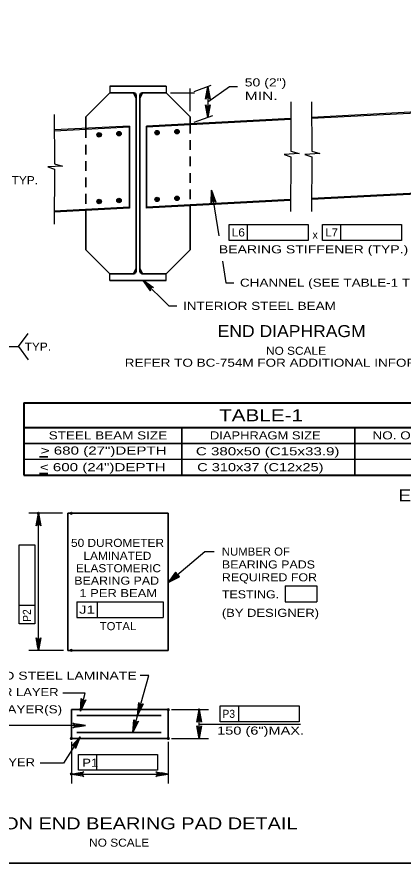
# Model space of a CAD drawing. Extents: x -11 to 79, y -154 to 0.
# Drawn here: x 46.09 to 51.83, y -65.25 to -52.68 of the extents above; entities that cross this region are included whole.
import ezdxf
from ezdxf.enums import TextEntityAlignment as Align

# ---------------------------------------------------------------- set-up
doc = ezdxf.new("R2010")
doc.units = 0
doc.header["$LTSCALE"] = 0.048
doc.header["$PDMODE"] = 32
doc.header["$PDSIZE"] = 0.024
doc.linetypes.add('MEDIUM_DASHED', pattern=[4.5, 3, -1.5])
for name, color, linetype, lineweight in [('1', 7, 'Continuous', 25), ('2', 7, 'Continuous', 35), ('3', 7, 'Continuous', 25), ('4', 7, 'Continuous', 25), ('5', 7, 'Continuous', 25), ('6', 7, 'Continuous', 25), ('7', 7, 'Continuous', 35)]:
    doc.layers.add(name, color=color, linetype=linetype, lineweight=lineweight)

msp = doc.modelspace()

# ---------------------------------------------------------------- hatches: boundary and pattern name
at = {"layer": '2'}
for points in [[(46.394, -60.14675), (46.4255, -60.14675), (46.40975, -60.05225)], [(48.34192, -61.08083), (48.50833, -60.99875), (48.45008, -60.93008)], [(46.394, -61.99592), (46.4255, -61.99592), (46.40975, -62.09042)], [(47.003, -63.91), (47.003, -63.94417), (46.90067, -63.92708)], [(48.23967, -63.91), (48.23967, -63.94417), (48.34192, -63.92708)]]:
    msp.add_hatch(color=256, dxfattribs=at).paths.add_polyline_path(points)
at = {"layer": '3'}
for points in [[(48.90933, -53.83183), (48.94933, -53.83183), (48.92933, -53.71183)], [(48.90933, -54.05008), (48.94933, -54.05008), (48.92933, -54.17008)], [(48.98508, -55.37192), (49.02458, -55.36583), (48.98658, -55.25025)], [(48.03867, -56.69133), (48.06667, -56.66283), (47.96717, -56.59292)], [(47.07742, -62.8995), (47.04442, -62.891), (47.03542, -62.99433)], [(48.78308, -63.07692), (48.81717, -63.07692), (48.80017, -62.97458)], [(48.78308, -63.29675), (48.81717, -63.29675), (48.80017, -63.39908)], [(46.99225, -63.46817), (46.96333, -63.45008), (47.03208, -63.37242)]]:
    msp.add_hatch(color=256, dxfattribs=at).paths.add_polyline_path(points)
at = {"layer": '5'}
for points in [[(47.93692, -62.94708), (47.89892, -62.93658), (47.88642, -63.05567)], [(46.99283, -63.187), (46.99283, -63.22633), (47.11092, -63.20667)], [(47.86342, -63.20292), (47.8255, -63.19242), (47.813, -63.3115)]]:
    msp.add_hatch(color=256, dxfattribs=at).paths.add_polyline_path(points)

# ---------------------------------------------------------------- linework, layer by layer
at = {"layer": '1', "lineweight": 35}
msp.add_lwpolyline([(35.75, -65.25), (67.25, -65.25), (67.25, -44.75), (35.75, -44.75)], close=True, dxfattribs=at)
at = {"layer": '2', "lineweight": 25}
for p, q in [((46.76658, -60.05225), (46.26792, -60.05225)), ((48.34192, -61.08083), (48.8845, -60.6205)), ((48.88442, -60.6205), (49.0245, -60.6205)), ((46.78533, -62.09042), (46.26792, -62.09042)), ((46.90067, -63.44825), (46.90067, -64.06875)), ((48.34192, -63.44825), (48.34192, -64.06875)), ((46.90067, -63.92708), (48.34192, -63.92708))]:
    msp.add_line(p, q, dxfattribs=at)
for points in [[(48.92933, -53.71183), (48.96425, -53.89825), (48.95433, -53.88392), (48.94183, -53.8765), (48.92933, -53.87433), (48.91683, -53.8765), (48.90433, -53.88392), (48.89442, -53.89825), (48.92933, -53.71183), (48.90433, -53.88392), (48.91683, -53.8765), (48.92933, -53.71183), (48.92933, -53.87433), (48.94183, -53.8765), (48.92933, -53.71183), (48.95433, -53.88392)], [(48.92933, -54.17008), (48.89442, -53.98367), (48.90433, -53.998), (48.91683, -54.00542), (48.92933, -54.00758), (48.94183, -54.00542), (48.95433, -53.998), (48.96425, -53.98367), (48.92933, -54.17008), (48.95433, -53.998), (48.94183, -54.00542), (48.92933, -54.17008), (48.92933, -54.00758), (48.91683, -54.00542), (48.92933, -54.17008), (48.90433, -53.998)], [(48.98658, -55.25025), (49.0495, -55.42917), (49.0375, -55.4165), (49.024, -55.41108), (49.01133, -55.41083), (48.99925, -55.41492), (48.98808, -55.42408), (48.98042, -55.43983), (48.98658, -55.25025), (48.98808, -55.42408), (48.99925, -55.41492), (48.98658, -55.25025), (49.01133, -55.41083), (49.024, -55.41108), (48.98658, -55.25025), (49.0375, -55.4165)], [(47.96708, -56.59292), (48.1245, -56.69875), (48.10725, -56.69575), (48.09325, -56.6995), (48.08292, -56.70683), (48.07567, -56.71725), (48.07217, -56.73142), (48.0755, -56.74858), (47.96708, -56.59292), (48.07217, -56.73142), (48.07567, -56.71725), (47.96708, -56.59292), (48.08292, -56.70683), (48.09325, -56.6995), (47.96708, -56.59292), (48.10725, -56.69575)], [(46.40975, -60.05225), (46.44467, -60.23867), (46.43475, -60.22433), (46.42225, -60.21692), (46.40975, -60.21475), (46.39725, -60.21692), (46.38475, -60.22433), (46.37483, -60.23867), (46.40975, -60.05225), (46.38475, -60.22433), (46.39725, -60.21692), (46.40975, -60.05225), (46.40975, -60.21475), (46.42225, -60.21692), (46.40975, -60.05225), (46.43475, -60.22433)], [(48.34192, -61.08083), (48.46142, -60.93358), (48.45692, -60.9505), (48.45942, -60.96475), (48.46583, -60.97567), (48.47558, -60.98383), (48.48925, -60.98858), (48.50667, -60.98692), (48.34192, -61.08083), (48.48925, -60.98858), (48.47558, -60.98383), (48.34192, -61.08083), (48.46583, -60.97567), (48.45942, -60.96475), (48.34192, -61.08083), (48.45692, -60.9505)], [(46.40975, -62.09042), (46.37483, -61.904), (46.38475, -61.91833), (46.39725, -61.92575), (46.40975, -61.92792), (46.42225, -61.92575), (46.43475, -61.91833), (46.44467, -61.904), (46.40975, -62.09042), (46.43475, -61.91833), (46.42225, -61.92575), (46.40975, -62.09042), (46.40975, -61.92792), (46.39725, -61.92575), (46.40975, -62.09042), (46.38475, -61.91833)], [(47.03542, -62.99433), (47.04808, -62.80508), (47.05417, -62.8215), (47.06442, -62.83175), (47.07592, -62.837), (47.08858, -62.838), (47.10258, -62.834), (47.11575, -62.8225), (47.03542, -62.99433), (47.10258, -62.834), (47.08858, -62.838), (47.03542, -62.99433), (47.07592, -62.837), (47.06442, -62.83175), (47.03542, -62.99433), (47.05417, -62.8215)], [(47.88642, -63.05567), (47.90242, -62.86667), (47.90817, -62.88317), (47.91825, -62.89367), (47.92975, -62.89908), (47.94233, -62.90033), (47.95642, -62.8965), (47.96983, -62.88533), (47.88642, -63.05567), (47.95642, -62.8965), (47.94233, -62.90033), (47.88642, -63.05567), (47.92975, -62.89908), (47.91825, -62.89367), (47.88642, -63.05567), (47.90817, -62.88317)], [(48.80017, -62.96983), (48.83508, -63.15625), (48.82517, -63.14192), (48.81267, -63.1345), (48.80017, -63.13233), (48.78767, -63.1345), (48.77517, -63.14192), (48.76525, -63.15625), (48.80017, -62.96983), (48.77517, -63.14192), (48.78767, -63.1345), (48.80017, -62.96983), (48.80017, -63.13233), (48.81267, -63.1345), (48.80017, -62.96983), (48.82517, -63.14192)], [(47.11092, -63.20667), (46.9245, -63.24158), (46.93883, -63.23167), (46.94625, -63.21917), (46.94842, -63.20667), (46.94625, -63.19417), (46.93883, -63.18167), (46.9245, -63.17175), (47.11092, -63.20667), (46.93883, -63.18167), (46.94625, -63.19417), (47.11092, -63.20667), (46.94842, -63.20667), (46.94625, -63.21917), (47.11092, -63.20667), (46.93883, -63.23167)], [(47.81558, -63.3115), (47.83158, -63.1225), (47.83742, -63.139), (47.84742, -63.1495), (47.85892, -63.15492), (47.87158, -63.15617), (47.88558, -63.15233), (47.899, -63.14117), (47.81558, -63.3115), (47.88558, -63.15233), (47.87158, -63.15617), (47.81558, -63.3115), (47.85892, -63.15492), (47.84742, -63.1495), (47.81558, -63.3115), (47.83742, -63.139)], [(48.80017, -63.39908), (48.76525, -63.21267), (48.77517, -63.227), (48.78767, -63.23442), (48.80017, -63.23658), (48.81267, -63.23442), (48.82517, -63.227), (48.83508, -63.21267), (48.80017, -63.39908), (48.82517, -63.227), (48.81267, -63.23442), (48.80017, -63.39908), (48.80017, -63.23658), (48.78767, -63.23442), (48.80017, -63.39908), (48.77517, -63.227)], [(47.03208, -63.37242), (46.96283, -63.549), (46.962, -63.5315), (46.95533, -63.51858), (46.94592, -63.51017), (46.93417, -63.50533), (46.91958, -63.505), (46.90358, -63.51192), (47.03208, -63.37242), (46.91958, -63.505), (46.93417, -63.50533), (47.03208, -63.37242), (46.94592, -63.51017), (46.95533, -63.51858), (47.03208, -63.37242), (46.962, -63.5315)], [(46.90067, -63.92708), (47.08708, -63.89217), (47.07275, -63.90208), (47.06533, -63.91458), (47.06317, -63.92708), (47.06533, -63.93958), (47.07275, -63.95208), (47.08708, -63.962), (46.90067, -63.92708), (47.07275, -63.95208), (47.06533, -63.93958), (46.90067, -63.92708), (47.06317, -63.92708), (47.06533, -63.91458), (46.90067, -63.92708), (47.07275, -63.90208)], [(48.34192, -63.92708), (48.1555, -63.962), (48.16983, -63.95208), (48.17725, -63.93958), (48.17942, -63.92708), (48.17725, -63.91458), (48.16983, -63.90208), (48.1555, -63.89217), (48.34192, -63.92708), (48.16983, -63.90208), (48.17725, -63.91458), (48.34192, -63.92708), (48.17942, -63.92708), (48.17725, -63.93958), (48.34192, -63.92708), (48.16983, -63.95208)]]:
    msp.add_lwpolyline(points, dxfattribs=at)
for points in [[(46.394, -60.14675), (46.4255, -60.14675), (46.40975, -60.05225)], [(48.34192, -61.08083), (48.50833, -60.99875), (48.45008, -60.93008)], [(46.394, -61.99592), (46.4255, -61.99592), (46.40975, -62.09042)], [(47.003, -63.91), (47.003, -63.94417), (46.90067, -63.92708)], [(48.23967, -63.91), (48.23967, -63.94417), (48.34192, -63.92708)]]:
    msp.add_lwpolyline(points, close=True, dxfattribs=at)
at = {"layer": '3'}
for p, q in [((48.37483, -53.80708), (48.73183, -53.80708)), ((48.66758, -54.08075), (48.66758, -53.74242)), ((48.72633, -53.78575), (48.98183, -53.69275)), ((48.92933, -53.941), (49.25358, -53.71083)), ((48.92933, -53.71183), (48.92933, -54.17008)), ((49.25358, -53.71083), (49.37358, -53.71083)), ((50.1635, -53.93975), (50.16592, -54.67392)), ((48.72633, -54.244), (49.00583, -54.14225)), ((50.16583, -54.75575), (50.161, -55.57)), ((50.59483, -54.70917), (50.374, -54.72142)), ((50.374, -54.72142), (50.47442, -54.75575)), ((50.47442, -54.75575), (50.46958, -55.57)), ((46.6495, -54.94208), (46.64467, -55.75633)), ((48.9865, -55.25025), (49.09133, -55.93092)), ((49.24558, -55.76325), (50.42142, -55.76325)), ((49.51942, -55.99942), (49.51942, -55.76325)), ((50.42142, -55.76325), (50.42142, -55.99942)), ((50.63342, -55.76325), (51.80925, -55.76325)), ((50.90725, -55.99942), (50.90725, -55.76325)), ((51.80925, -55.76325), (51.80925, -55.99942)), ((49.14917, -56.30708), (49.19833, -56.62658)), ((49.19842, -56.62658), (49.31842, -56.62658)), ((46.11608, -57.57725), (46.25875, -57.38375)), ((45.19417, -57.57725), (46.11608, -57.57725)), ((46.11608, -57.57725), (46.25875, -57.77083)), ((46.19175, -59.25067), (52.95675, -59.25067)), ((46.40975, -62.09042), (46.40975, -60.05225)), ((46.12233, -61.69758), (46.12233, -60.52175)), ((46.12233, -60.52175), (46.35858, -60.52175)), ((46.35858, -60.52175), (46.35858, -61.69758)), ((50.07925, -61.1315), (50.551, -61.1315)), ((50.07925, -61.1315), (50.07925, -61.36775)), ((50.551, -61.1315), (50.551, -61.36775)), ((46.35858, -61.42375), (46.12233, -61.42375)), ((46.97958, -61.36633), (48.26558, -61.36633)), ((46.97958, -61.36633), (46.97958, -61.60258)), ((47.282, -61.36633), (47.282, -61.60258)), ((48.26558, -61.36633), (48.26558, -61.60258)), ((50.07925, -61.36775), (50.551, -61.36775)), ((46.35858, -61.69758), (46.12233, -61.69758)), ((46.97958, -61.60258), (48.26558, -61.60258)), ((47.10433, -62.72683), (46.77467, -62.72683)), ((47.03542, -62.99433), (47.10433, -62.72683)), ((48.39117, -62.96983), (48.94175, -62.96983)), ((48.80017, -63.39908), (48.80017, -62.96983)), ((49.115, -62.91542), (50.29083, -62.91542)), ((49.115, -63.15158), (49.115, -62.91542)), ((49.38883, -63.15158), (49.38883, -62.91542)), ((50.29083, -62.91542), (50.29083, -63.15158)), ((48.80017, -63.18442), (50.30642, -63.18442)), ((50.29083, -63.15158), (49.115, -63.15158)), ((47.03208, -63.37242), (46.78533, -63.76675)), ((48.39117, -63.39908), (48.94175, -63.39908)), ((47.008, -63.87167), (47.008, -63.63542)), ((47.008, -63.63542), (48.18375, -63.63542)), ((47.28175, -63.87167), (47.28175, -63.63542)), ((48.18375, -63.63542), (48.18375, -63.87167)), ((46.78533, -63.76675), (46.437, -63.76675)), ((48.18375, -63.87167), (47.008, -63.87167))]:
    msp.add_line(p, q, dxfattribs=at)
at = {"layer": '3', "lineweight": 40}
for p, q in [((46.19175, -58.41233), (52.95675, -58.41233)), ((46.19175, -58.41233), (46.19175, -59.48692)), ((46.19175, -58.77825), (52.95675, -58.77825)), ((46.19175, -59.48692), (52.95675, -59.48692))]:
    msp.add_line(p, q, dxfattribs=at)
at = {"layer": '3', "lineweight": 35}
for p, q in [((48.54108, -58.77825), (48.54108, -59.48692)), ((51.11758, -58.77825), (51.11758, -59.48692)), ((46.19175, -59.0145), (52.95675, -59.0145)), ((46.54875, -59.21517), (46.42533, -59.21517)), ((46.54875, -59.46042), (46.42533, -59.46042))]:
    msp.add_line(p, q, dxfattribs=at)
at = {"layer": '3'}
for points in [[(48.90933, -53.83183), (48.94933, -53.83183), (48.92933, -53.71183)], [(48.90933, -54.05008), (48.94933, -54.05008), (48.92933, -54.17008)], [(48.98508, -55.37192), (49.02458, -55.36583), (48.98658, -55.25025)], [(48.03867, -56.69133), (48.06667, -56.66283), (47.96717, -56.59292)], [(47.07742, -62.8995), (47.04442, -62.891), (47.03542, -62.99433)], [(48.78308, -63.07692), (48.81717, -63.07692), (48.80017, -62.97458)], [(48.78308, -63.29675), (48.81717, -63.29675), (48.80017, -63.39908)], [(46.99225, -63.46817), (46.96333, -63.45008), (47.03208, -63.37242)]]:
    msp.add_lwpolyline(points, close=True, dxfattribs=at)
for points in [[(50.47208, -53.93975), (50.4745, -54.67392), (50.59483, -54.70917)], [(46.64708, -54.12608), (46.64958, -54.86025), (46.76983, -54.89558), (46.549, -54.90775), (46.6495, -54.94208)], [(50.16592, -54.67392), (50.28625, -54.70917), (50.06542, -54.72142), (50.16583, -54.75575)], [(50.42142, -55.99942), (49.24558, -55.99942), (49.24558, -55.76325)], [(51.80925, -55.99942), (50.63342, -55.99942), (50.63342, -55.76325)], [(47.96708, -56.59292), (48.35108, -56.97067), (48.47108, -56.97067)]]:
    msp.add_lwpolyline(points, dxfattribs=at)
msp.add_point((48.80017, -62.96983), dxfattribs=at)
at = {"layer": '4', "lineweight": 35}
for p, q in [((47.47267, -53.80708), (47.11642, -54.16342)), ((47.47267, -53.70708), (48.31125, -53.70708)), ((47.47267, -53.80708), (47.82883, -53.80708)), ((47.82508, -53.80708), (47.86442, -53.88583)), ((47.95892, -53.80708), (47.91958, -53.88583)), ((47.95517, -53.80708), (48.31125, -53.80708)), ((48.31125, -53.80708), (48.66758, -54.16342)), ((47.86442, -53.84267), (47.86442, -56.45733)), ((47.91958, -53.84267), (47.91958, -56.45733)), ((47.11642, -54.16342), (47.11642, -54.33308)), ((48.66758, -54.16342), (48.66758, -54.26533)), ((47.766, -54.29925), (47.766, -55.51967)), ((48.018, -54.29925), (48.018, -55.51967)), ((47.11642, -55.55358), (47.11642, -56.13667)), ((48.66758, -55.48583), (48.66758, -56.13667)), ((47.11642, -56.13667), (47.47267, -56.49292)), ((48.31125, -56.49292), (48.66758, -56.13667)), ((47.82508, -56.49292), (47.86442, -56.41417)), ((47.95892, -56.49292), (47.91958, -56.41417)), ((47.47267, -56.49292), (47.82883, -56.49292)), ((47.95517, -56.49292), (48.31125, -56.49292)), ((47.47267, -56.59292), (48.31125, -56.59292)), ((46.84808, -60.05225), (46.84808, -62.09042)), ((46.84808, -60.05225), (48.34192, -60.05225)), ((48.34192, -60.05225), (48.34192, -62.09042)), ((46.84808, -62.09042), (48.34192, -62.09042)), ((48.34192, -62.96983), (46.90067, -62.96983)), ((46.90067, -62.96983), (46.90067, -63.39908)), ((48.34192, -63.39908), (48.34192, -62.96983)), ((48.23492, -63.05567), (46.98008, -63.05567)), ((48.23492, -63.3115), (46.98008, -63.3115)), ((46.90067, -63.39908), (48.34192, -63.39908))]:
    msp.add_line(p, q, dxfattribs=at)
at = {"layer": '4', "linetype": 'MEDIUM_DASHED', "lineweight": 35}
for p, q in [((48.66758, -54.26533), (48.66758, -55.48583)), ((47.11642, -54.33308), (47.11642, -55.55358))]:
    msp.add_line(p, q, dxfattribs=at)
at = {"layer": '4', "lineweight": 35}
for centre, start, end in [((47.82882, -53.84268), 0, 90), ((47.95509, -53.84268), 90, 180), ((47.82882, -56.45735), 270, 0), ((47.95509, -56.45735), 180, 270)]:
    msp.add_arc(centre, 0.03558, start, end, dxfattribs=at)
at = {"layer": '5'}
for p, q in [((47.47267, -53.70708), (47.47267, -53.80708)), ((48.31125, -53.70708), (48.31125, -53.80708)), ((52.6305, -54.05867), (50.47283, -54.17125)), ((52.6305, -54.07442), (50.47283, -54.18692)), ((47.766, -54.29925), (46.64783, -54.35758)), ((50.16433, -54.18733), (48.018, -54.29925)), ((50.16433, -54.20308), (48.018, -54.315)), ((47.766, -54.315), (46.64792, -54.37325)), ((52.6305, -55.27917), (50.47067, -55.39183)), ((52.6305, -55.26342), (50.47075, -55.376)), ((50.16208, -55.39217), (48.018, -55.50392)), ((50.162, -55.40792), (48.018, -55.51967)), ((47.766, -55.51967), (46.64567, -55.57817)), ((47.766, -55.50392), (46.64575, -55.56242)), ((47.47267, -56.59292), (47.47267, -56.49292)), ((48.31125, -56.59292), (48.31125, -56.49292)), ((47.81558, -63.3115), (48.05108, -62.46058)), ((47.11083, -63.20667), (45.89942, -63.20667))]:
    msp.add_line(p, q, dxfattribs=at)
for points in [[(47.93692, -62.94708), (47.89892, -62.93658), (47.88642, -63.05567)], [(46.99283, -63.187), (46.99283, -63.22633), (47.11092, -63.20667)], [(47.86342, -63.20292), (47.8255, -63.19242), (47.813, -63.3115)]]:
    msp.add_lwpolyline(points, close=True, dxfattribs=at)
for centre, radius in [((47.31322, -54.42938), 0.03333), ((47.31322, -54.42938), 0.025), ((47.31322, -54.42938), 0.01667), ((47.31322, -54.42938), 0.00833), ((47.60849, -54.41341), 0.03333), ((47.60849, -54.41341), 0.025), ((47.60849, -54.41341), 0.01667), ((47.60849, -54.41341), 0.00833), ((48.17542, -54.39723), 0.03333), ((48.17542, -54.39723), 0.025), ((48.17542, -54.39723), 0.01667), ((48.17542, -54.39723), 0.00833), ((48.47069, -54.38201), 0.03333), ((48.47069, -54.38201), 0.025), ((48.47069, -54.38201), 0.01667), ((48.47069, -54.38201), 0.00833), ((47.31322, -55.4215), 0.03333), ((47.31322, -55.4215), 0.025), ((47.31322, -55.4215), 0.01667), ((47.31322, -55.4215), 0.00833), ((47.60849, -55.40553), 0.03333), ((47.60849, -55.40553), 0.025), ((47.60849, -55.40553), 0.01667), ((47.60849, -55.40553), 0.00833), ((48.17542, -55.38936), 0.03333), ((48.17542, -55.38936), 0.025), ((48.17542, -55.38936), 0.01667), ((48.17542, -55.38936), 0.00833), ((48.47069, -55.37414), 0.03333), ((48.47069, -55.37414), 0.025), ((48.47069, -55.37414), 0.01667), ((48.47069, -55.37414), 0.00833)]:
    msp.add_circle(centre, radius, dxfattribs=at)
at = {"layer": '6'}
msp.add_line((48.051, -62.46058), (47.92267, -62.46058), dxfattribs=at)
at = {"layer": '7'}
for p in [(46.40975, -60.05225), (46.90067, -60.05225), (46.90067, -62.09042), (48.34192, -62.96983), (46.90067, -63.39908), (48.34192, -63.39908), (46.90067, -63.92708)]:
    msp.add_point(p, dxfattribs=at)

# ---------------------------------------------------------------- texts
at = {"layer": '3'}
for s, height, width, p in [('50 (2")', 0.12, 1.3, (49.47875, -53.71108)), ('MIN. ', 0.12, 1.45, (49.47875, -53.91108)), ('TYP.', 0.12, 1.1, (46.0125, -55.16342)), ('BEARING STIFFENER (TYP.)', 0.12, 1.3, (49.09417, -56.19108)), ('CHANNEL (SEE TABLE-1 THIS SHEET)', 0.12, 1.25, (49.40833, -56.68667)), ('INTERIOR STEEL BEAM', 0.12, 1.25, (48.561, -57.03075)), ('TYP.', 0.12, 1.1, (46.20608, -57.63733)), ('ELASTOMERIC BEARING PAD N0TES:', 0.1772, 1.2, (51.76425, -59.87475)), ('NUMBER OF', 0.12, 1.05, (49.13933, -60.68192)), ('BEARING PADS', 0.12, 1.15, (49.13933, -60.87317)), ('REQUIRED FOR', 0.12, 1.15, (49.13933, -61.06433)), ('TESTING.', 0.12, 1.15, (49.13933, -61.317)), ('(BY DESIGNER)', 0.12, 1.2, (49.13933, -61.592))]:
    msp.add_text(s, height=height, dxfattribs=dict(at, width=width)).set_placement(p)
for s, height, width, p in [('L6', 0.12, 1.1, (49.38304, -55.94008)), ('L7', 0.12, 1.05, (50.77092, -55.94008)), ('END DIAPHRAGM', 0.1772, 1.1, (50.177, -57.43467)), ('NO SCALE', 0.12, 1.1, (50.24154, -57.69842)), ('REFER TO BC-754M FOR ADDITIONAL INFORMATION', 0.12, 1.25, (50.25187, -57.87575)), ('TABLE-1', 0.1772, 1.3, (49.72171, -58.68525)), ('STEEL BEAM SIZE', 0.12, 1.25, (47.4445, -58.95542)), ('DIAPHRAGM SIZE', 0.12, 1.2, (49.78462, -58.95542)), ('NO. OF BOLTS', 0.12, 1.25, (52.08125, -58.95533)), ('> 680 (27")DEPTH', 0.12, 1.4, (47.38104, -59.18083)), ('C 380x50 (C15x33.9)', 0.12, 1.4, (49.82012, -59.19167)), ('< 600 (24")DEPTH', 0.12, 1.4, (47.36771, -59.42783)), ('C 310x37 (C12x25)', 0.12, 1.35, (49.71121, -59.42783)), ('50 DUROMETER', 0.12, 1.1, (47.58696, -60.55258)), ('LAMINATED', 0.12, 1.1, (47.58529, -60.74458)), ('ELASTOMERIC', 0.12, 1.1, (47.60117, -60.92917)), ('BEARING PAD', 0.12, 1.15, (47.5745, -61.11375)), ('1 PER BEAM', 0.12, 1.2, (47.598, -61.29842)), ('TOTAL', 0.12, 1.05, (47.59362, -61.78942)), ('3.04 (11 GAGE) BONDED STEEL LAMINATE', 0.12, 1.3, (45.73992, -62.52567)), ('5 (3/16")COVER LAYER', 0.12, 1.2, (45.65908, -62.76983)), ('INTERIOR LAYER(S)', 0.12, 1.25, (45.79329, -63.0255)), ('P3', 0.12, 0.95, (49.24112, -63.09225)), ('150 (6")MAX.', 0.12, 1.35, (49.71467, -63.34167)), ('5 (3/16")COVER LAYER', 0.12, 1.2, (45.30867, -63.81217)), ('P1', 0.12, 1.2, (47.18096, -63.81842)), ('EXPANSION END BEARING PAD DETAIL', 0.1772, 1.25, (47.43287, -64.749)), ('NO SCALE', 0.12, 1.1, (47.61121, -65.00658))]:
    msp.add_text(s, height=height, dxfattribs=dict(at, width=width)).set_placement(p, align=Align.CENTER)
msp.add_text('x', height=0.12, dxfattribs=at).set_placement((50.486, -55.97342))
for s, rotation, width, p in [('J1', 359.938, 1.4, (47.13319, -61.54455)), ('P2', 90, 0.95, (46.29917, -61.57212))]:
    msp.add_text(s, height=0.12, rotation=rotation, dxfattribs=dict(at, width=width)).set_placement(p, align=Align.CENTER)

doc.saveas('drawing.dxf')
